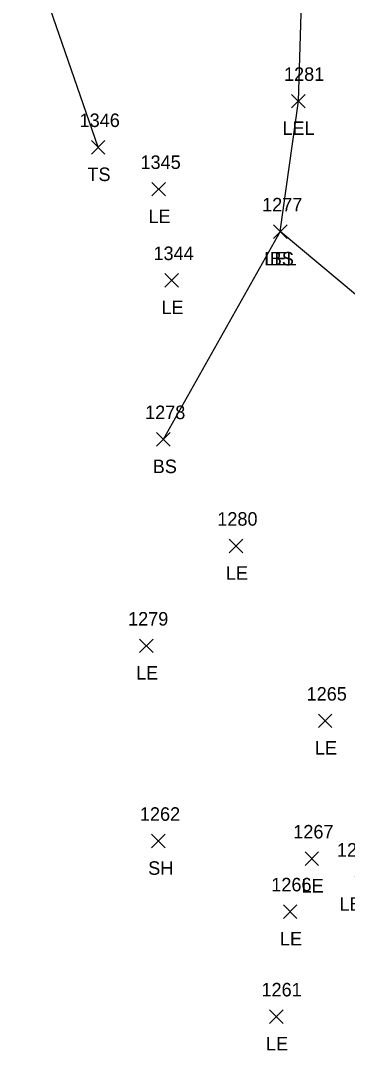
# Model space of a CAD drawing. Extents: x 1545627 to 1546562, y 571176 to 576667.
# Drawn here: x 1546012.3 to 1546060.7, y 572062.1 to 572214.6 of the extents above; entities that cross this region are included whole.
import ezdxf

# ---------------------------------------------------------------- set-up
doc = ezdxf.new("R2010")
doc.units = 0
for name, color, linetype in [('L_A', 7, 'Continuous'), ('L_I', 7, 'Continuous'), ('L_TIC', 7, 'Continuous'), ('LARO', 7, 'Continuous'), ('LELB', 7, 'Continuous')]:
    doc.layers.add(name, color=color, linetype=linetype)

msp = doc.modelspace()

# ---------------------------------------------------------------- linework, layer by layer
at = {"layer": 'L_TIC'}
for points in [[(1546052.43, 572201.66), (1546054.43, 572203.66)], [(1546054.43, 572201.66), (1546052.43, 572203.66)], [(1546022.82, 572194.83), (1546024.82, 572196.83)], [(1546024.82, 572194.83), (1546022.82, 572196.83)], [(1546031.77, 572188.62), (1546033.77, 572190.62)], [(1546033.77, 572188.62), (1546031.77, 572190.62)], [(1546049.76, 572182.34), (1546051.76, 572184.34)], [(1546051.76, 572182.34), (1546049.76, 572184.34)], [(1546049.76, 572182.34), (1546051.76, 572184.34)], [(1546051.76, 572182.34), (1546049.76, 572184.34)], [(1546033.69, 572175.13), (1546035.69, 572177.13)], [(1546035.69, 572175.13), (1546033.69, 572177.13)], [(1546032.45, 572151.59), (1546034.45, 572153.59)], [(1546034.45, 572151.59), (1546032.45, 572153.59)], [(1546043.22, 572135.81), (1546045.22, 572137.81)], [(1546045.22, 572135.81), (1546043.22, 572137.81)], [(1546029.94, 572121.02), (1546031.94, 572123.02)], [(1546031.94, 572121.02), (1546029.94, 572123.02)], [(1546056.39, 572109.91), (1546058.39, 572111.91)], [(1546058.39, 572109.91), (1546056.39, 572111.91)], [(1546031.73, 572092.12), (1546033.73, 572094.12)], [(1546033.73, 572092.12), (1546031.73, 572094.12)], [(1546054.42, 572089.5), (1546056.42, 572091.5)], [(1546056.42, 572089.5), (1546054.42, 572091.5)], [(1546051.22, 572081.67), (1546053.22, 572083.67)], [(1546053.22, 572081.67), (1546051.22, 572083.67)], [(1546049.16, 572066.12), (1546051.16, 572068.12)], [(1546051.16, 572066.12), (1546049.16, 572068.12)]]:
    msp.add_lwpolyline(points, dxfattribs=at)
at = {"layer": 'LARO'}
msp.add_lwpolyline([(1546061.88, 572087.81), (1546067.17, 572106.31), (1546070.63, 572137.24), (1546070.36, 572157.28), (1546064.88, 572171.54), (1546050.76, 572183.34), (1546053.43, 572202.66), (1546054.72, 572244.86), (1546049.25, 572294.69), (1546045.28, 572306.42), (1546036.98, 572305.38)], dxfattribs=at)
at = {"layer": 'LELB'}
for points in [[(1546023.82, 572195.83), (1546013.19, 572226.53), (1546014.26, 572243.42), (1546012.34, 572265.14), (1546016.06, 572277.82), (1546029.49, 572296.38), (1546039.24, 572305.63), (1546043.68, 572305.31)], [(1546050.76, 572183.34), (1546033.45, 572152.59)]]:
    msp.add_lwpolyline(points, dxfattribs=at)

# ---------------------------------------------------------------- texts
at = {"layer": 'L_A'}
for s, p in [('LEL', (1546051.07, 572197.66)), ('TS', (1546022.23, 572190.83)), ('LE', (1546031.26, 572184.62)), ('LEL', (1546048.4, 572178.34)), ('BS', (1546049.2, 572178.34)), ('LE', (1546033.18, 572171.13)), ('BS', (1546031.89, 572147.59)), ('LE', (1546042.71, 572131.81)), ('LE', (1546029.42, 572117.02)), ('LE', (1546055.88, 572105.91)), ('SH', (1546031.22, 572088.12)), ('LE', (1546053.91, 572085.5)), ('LEL', (1546059.52, 572082.81)), ('LE', (1546050.71, 572077.67)), ('LE', (1546048.64, 572062.12))]:
    msp.add_text(s, height=2, dxfattribs=at).set_placement(p)
at = {"layer": 'L_I'}
for s, p in [('1281', (1546051.31, 572205.66)), ('1346', (1546021.07, 572198.83)), ('1345', (1546030.08, 572192.62)), ('1277', (1546048.07, 572186.34)), ('1277', (1546048.07, 572186.34)), ('1344', (1546032, 572179.13)), ('1278', (1546030.76, 572155.59)), ('1280', (1546041.44, 572139.81)), ('1279', (1546028.24, 572125.02)), ('1265', (1546054.65, 572113.91)), ('1262', (1546029.99, 572096.12)), ('1267', (1546052.68, 572093.5)), ('1268', (1546059.14, 572090.81)), ('1266', (1546049.43, 572085.67)), ('1261', (1546047.98, 572070.12))]:
    msp.add_text(s, height=2, dxfattribs=at).set_placement(p)

doc.saveas('drawing.dxf')
